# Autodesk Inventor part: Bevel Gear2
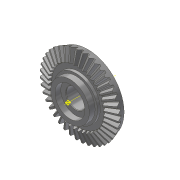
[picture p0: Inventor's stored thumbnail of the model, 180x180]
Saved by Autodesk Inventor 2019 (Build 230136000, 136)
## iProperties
Created: 2019-01
Part Number: Bevel Gear2
Material: Steel, Mild
Document SubType Name: Modeling
Designer: m.vorobev
Categories: <?xml version="1.0" encoding="UTF-16"?> <MemberInstance><Categories><FamilyTemplate><FamilyTemplateParameter ValueType="xs:double" Id="1" ObjectReferenceKey="da
Mass: 60.9118 g
Surface Area: 34.3074 cm^2
Volume: 7.7496 cm^3
Density: 7.86 g/cm^3
Appearance: Steel
CustomPartVersion: 1
Author: m.vorobev
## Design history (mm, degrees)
node "Top Point"
node "Mesh Plane2"
sketch "Teeth Body Sketch"
  geometry: L1 (0, 0)-(78.414, -32.531); L2 (78.414, -32.531)-(81.321, -24.225); L3 (81.321, -24.225)-(0, 0); L4 (80, -28)-(0, 0); L5 (55.286, -22.935)-(57.335, -17.079); L6 (78.414, -32.531)-(55.286, -22.935); L7 (81.321, -24.225)-(57.335, -17.079); L8 (0, -39.387)-(0, 6.564) reference; L9 (0, -28)-(81.321, -28)
  constraints: 16 end point, 4 point on line, 3 perpendicular, 2 collinear, 1 horizontal alignment, 1 vertical alignment
  dimensions: "d0" = 160 diameter of L4.start L8 (= da_de); "d1" = 156.82864 diameter of L1.end L8 (= da_dfe); "d2" = 162.6428 diameter of L2.end L8 (= da_dae); "d3" = 25 distance between parallel lines of L2 L5 (= da_b); "d4" = 24.22457 vertical distance of L2.end L1.start (= da_ve)
revolve "Teeth Body" sketch "Teeth Body Sketch" stored, may be unused: angle "d5" = 90 deg
node "Start Point"
node "Tooth Plane"
sketch "Start Sketch"
  geometry: L1 (0, -23.505)-(0, 10.645) reference; L2 (-1.283, -5.856)-(1.283, -5.856); A1 r 84.219 centre (-82.286, -28.909) between (-1.283, -5.856) and (-5.905, 6.57); A2 r 84.219 centre (82.286, -28.909) between (5.905, 6.57) and (1.283, -5.856); A3 r 248.807 centre (0, -242.167) between (5.905, 6.57) and (-5.905, 6.57); 1 further point
  constraints: 6 point on circle, 3 centre point, 3 symmetric about line, 2 end point, 1 coincident, 1 perpendicular, 1 other
  dimensions: "d7" = 84.21912 radius of A1 (= fd_rr); "d8" = 82.28596 horizontal distance of point (0, -242.167) A1.centre (= fd_x); "d9" = 213.25785 vertical distance of point (0, -242.167) A1.centre (= fd_y); "d57" = 248.80709 radius of A3 (= 0.5 x fd_dva + 0.3 x da_he); "d58" = 236.31109 distance from line of A3.centre L2 (= 0.5 x fd_dva - 1.12 x da_he)
node "End Point"
  node "End Plane"
sketch "3D Sketch Right"
  node "Helical Curve Right" dims "d65" = 388.94171 (computed from da_dm, da_delta, da_beta), "d66" = 31.5, "d67" = 160 (= da_de), "d68" = -12.34122 (= -da_delta), "d69" = 8.40411 (computed from fd_loft, da_delta)
node "End Plane Right"
sketch "End Sketch Right"
  geometry: L1 (0, -204.954)-(0, 39.264) reference; L2 (-0.899, -3.862)-(0.899, -3.862); A1 r 59.025 centre (-57.67, -20.019) between (-0.899, -3.862) and (-4.138, 4.847); A2 r 59.025 centre (57.67, -20.019) between (4.138, 4.847) and (0.899, -3.862); A3 r 174.377 centre (0, -169.481) between (4.138, 4.847) and (-4.138, 4.847); 1 further point
  constraints: 6 point on circle, 3 centre point, 3 symmetric about line, 2 end point, 1 coincident, 1 perpendicular, 1 other
  dimensions: "d70" = 57.67036 horizontal distance of A3.centre A1.centre (computed from fd_x, fd_ratio); "d71" = 149.46241 vertical distance of point (0, -169.481) A1.centre (computed from fd_y, fd_ratio); "d72" = 59.02523 radius of A1 (computed from fd_rr, fd_ratio); "d73" = 165.61934 distance from line of point (0, -169.481) L2 (computed from d58, fd_ratio); "d74" = 174.3772 radius of A3 (computed from d57, fd_ratio)
feature "Loft Right" sketch "End Sketch Right" dims "d75" = 0, "d77" = 0, "d79" = 0, "d80" = 90 deg, "d85" = 20, "d92" = 90 deg, "d93" = 90 deg, "da_teethtype" = 0 [user parameter]
sketch "3D Sketch Left"
  node "Helical Curve Left" dims "d26" = 388.94171 (computed from da_dm, da_delta, da_beta), "d27" = 8.40411 (computed from fd_loft, da_delta), "d28" = 160 (= da_de), "d29" = -12.34122 (= -da_delta)
node "End Plane Left"
sketch "End Sketch Left" dims "d56" = 19.01874 (derived)
  geometry: L1 (0, -205.693)-(0, 40.091) reference; L2 (-0.899, -3.776)-(0.899, -3.776); A1 r 59.025 centre (-57.67, -19.933) between (-0.899, -3.776) and (-4.138, 4.932); A2 r 59.025 centre (57.67, -19.933) between (4.138, 4.932) and (0.899, -3.776); A3 r 174.377 centre (0, -169.396) between (4.138, 4.932) and (-4.138, 4.932); 2 further points; 1 other entity
  constraints: 6 point on circle, 3 centre point, 3 symmetric about line, 2 end point, 1 coincident, 2 other
  dimensions: "d30" = 59.02523 radius of A1 (computed from fd_rr, fd_ratio); "d31" = 57.67036 horizontal distance of point (0, -169.396) A1.centre (computed from fd_x, fd_ratio); "d32" = 149.46241 vertical distance of A1.centre point (0, -169.396) (computed from fd_y, fd_ratio); "d61" = 174.3772 radius of A3 (computed from d57, fd_ratio); "d62" = 165.61934 distance from line of point (0, -169.396) L2 (computed from d58, fd_ratio)
feature "Loft Left" sketch "End Sketch Left" dims "d35" = 0, "d37" = 0, "d39" = 0, "d40" = 90 deg, "d84" = 10, "d90" = 90 deg, "d91" = 90 deg, "da_teethtype" = 0 [user parameter]
sketch "Body Sketch"
  geometry: L1 (0, -35.038)-(0, -19.531) reference; L2 (78.414, -32.531)-(55.286, -22.935) reference; L3 (55.286, -22.935)-(0, -22.935); L4 (78.414, -32.531)-(0, -32.531)
  constraints: 4 end point, 2 perpendicular, 2 point on line
revolve "Fix Body" sketch "Body Sketch" stored, may be unused: angle "d46" = 90 deg
sketch "Sketch6"
  geometry: L1 (80, -28)-(0, 0) reference; L2 (0, -37.8)-(0, 6.3) reference
feature "Pitch Diameter" sketch "Sketch6" dims angle "d47" = 90 deg
sketch "Sketch8"
  geometry: L1 (55.286, -22.935)-(57.335, -17.079) reference; L2 (81.321, -24.225)-(57.335, -17.079) reference; L3 (78.414, -32.531)-(81.321, -24.225) reference; L4 (78.414, -32.531)-(55.286, -22.935) reference; L5 (78.414, -32.531)-(75.072, -42.079); L6 (75.072, -42.079)-(55.286, -42.079); L7 (55.286, -42.079)-(55.286, -22.935); L8 (78.414, -32.531)-(55.286, -22.935); L9 (77.682, -32.531)-(78.398, -32.531) reference; L10 (78.398, -32.531)-(79.868, -32.531); L11 (79.868, -32.531)-(79.868, -37.903); L12 (79.868, -37.903)-(78.398, -37.903); L13 (78.398, -37.903)-(78.398, -32.531); L14 (55.286, -42.079)-(20, -42.079); L15 (20, -42.079)-(20, -22.935); L16 (20, -22.935)-(55.286, -22.935); L17 (55.286, -22.935)-(55.286, -42.079); L18 (20, -22.935)-(45, -22.935); L19 (45, -22.935)-(45, -17.079); L20 (45, -17.079)-(20, -17.079); L21 (20, -17.079)-(20, -22.935); L22 (31, -17.079)-(40, -17.079); L23 (40, -17.079)-(40, -5.079); L24 (40, -5.079)-(31, -5.079); L25 (31, -5.079)-(31, -17.079); L26 (0, -50.495)-(0, 8.416) reference; 2 further points
  constraints: 40 end point, 9 equal length, 5 horizontal, 4 perpendicular, 1 collinear, 1 point on line, 1 vertical
  dimensions: "d95" = 25 distance from line of L1.end L6; "d96" = 19.29 deg angle of L5 L13 (derived); "d97" = 40 diameter of L21 L26; "d98" = 62 diameter of L25 L26; "d99" = 12 distance of L24.end L22.start; "d100" = 25 distance between parallel lines of L14 L22; "d101" = 90 diameter of L19 L26; "d102" = 80 diameter of L23 L26; "d103" = 37 distance between parallel lines of L14 L24 (derived)
revolve "Revolution3" sketch "Sketch8" stored, may be unused: angle "d104" = 90 deg
delete_face "Delete Face1"
chamfer "Chamfer1" distance "d105" = 1; stored, may be unused: second distance "d106" = 2, angle "d107" = 45 deg
sketch "Sketch9"
  geometry: L1 (-22.3, 6)-(-7.299, 6); L2 (-7.299, 6)-(-7.299, -6); L3 (-7.299, -6)-(-22.3, -6); L4 (-22.3, -6)-(-22.3, 6); C1 r 21 at (0, 0) reference; 2 further points
  constraints: 8 end point, 2 parallel, 1 horizontal, 1 horizontal alignment, 1 midpoint, 1 perpendicular
  dimensions: "d108" = 12 distance of L3.end L1.start; "d109" = 43.3 dimension on C1 L4
extrude "Extrusion1" cut sketch "Sketch9" extent not by distance; stored distance "d110" = 0; taper "d111" = 0 deg
body "Solid1"
feature "Loft" dims "d17" = 0, "d18" = 90 deg, "d19" = 0, "d20" = 90 deg, "d89" = 0, "da_teethtype" = 0 [user parameter]
pattern_circular "Circular Pattern" dims angle "d22" = 360 deg, "d88" = 0, "da_teethtype" = 0 [user parameter]
pattern_circular "Circular Pattern Right" dims angle "d82" = 360 deg, "da_teethtype" = 0 [user parameter]
pattern_circular "Circular Pattern Left" dims angle "d42" = 360 deg, "da_teethtype" = 0 [user parameter]
sketch "End Sketch"
  geometry: L1 (0, -15.359)-(0, 6.983) reference; L2 (-0.899, -3.862)-(0.899, -3.862); A1 r 59.025 centre (-57.67, -20.019) between (-0.899, -3.862) and (-4.138, 4.847); A2 r 59.025 centre (57.67, -20.019) between (4.138, 4.847) and (0.899, -3.862); A3 r 174.377 centre (0, -169.481) between (4.138, 4.847) and (-4.138, 4.847); 1 further point
  constraints: 6 point on circle, 3 centre point, 3 symmetric about line, 2 end point, 1 coincident, 1 other
  dimensions: "d12" = 59.02523 radius of A1 (computed from fd_rr, fd_ratio); "d15" = 57.67036 horizontal distance of A1.centre point (0, -169.481) (computed from fd_x, fd_ratio); "d16" = 149.46241 vertical distance of A1.centre point (0, -169.481) (computed from fd_y, fd_ratio); "d59" = 174.3772 radius of A3 (computed from d57, fd_ratio); "d60" = 165.61934 distance from line of A3.centre L2 (computed from d58, fd_ratio)
body "Srf1"
other parameters: "da_b" = 25 [user parameter; used in 2 equation terms], "da_de" = 160 [user parameter; used in 4 equation terms], "da_dae" = 162.6428 [user parameter; used in 2 equation terms], "da_dfe" = 156.82864 [user parameter; used in 1 equation term], "da_le" = 84.75848 [user parameter; used in 1 equation term], "da_omega" = 90 deg [user parameter; used in 1 equation term], "da_beta" = 0 [user parameter; used in 2 equation terms], "da_delta" = 12.34122 [user parameter; used in 8 equation terms], "da_alpha" = 20 deg [user parameter; used in 2 equation terms], "da_he" = 8.8 [user parameter; used in 4 equation terms], "da_ve" = 24.22457 [user parameter; used in 1 equation term], "fd_dv" = 484.33417 (computed from da_de, da_delta) [user parameter; used in 1 equation term], "fd_dva" = 492.33417 (computed from da_dae, da_delta) [user parameter; used in 3 equation terms], "fd_dvb" = 455.12525 (computed from fd_dv, da_alpha) [user parameter; used in 2 equation terms], "da_zv" = 1210.83543 [user parameter; used in 1 equation term], "fd_loft" = 25.44 (= da_b + 0.05 x da_he) [user parameter; used in 4 equation terms], "fd_ratio" = 7.00853 (computed from da_le, fd_loft) [user parameter; used in 15 equation terms], "fd_rr" = 84.21912 (computed from fd_dd, fd_dvb) [user parameter; used in 6 equation terms], "fd_angle" = 0.13117 (computed from da_zv) [user parameter; used in 4 equation terms], "fd_x1" = 3.17641 (computed from da_dvw, fd_angle) [user parameter; used in 1 equation term], "fd_y1" = 242.14625 (computed from da_dvw, fd_angle) [user parameter; used in 1 equation term], "fd_x2" = 79.10955 (computed from fd_rr, fd_angle2, fd_angle) [user parameter; used in 1 equation term], "fd_y2" = 28.88841 (computed from fd_rr, fd_angle2, fd_angle) [user parameter; used in 1 equation term], "fd_x" = 82.28596 (= fd_x1 + fd_x2) [user parameter; used in 4 equation terms], "fd_y" = 213.25785 (= fd_y1 - fd_y2) [user parameter; used in 4 equation terms], "fd_angle2" = 3.37008 (computed from fd_dvb, fd_dd, da_alpha) [user parameter; used in 2 equation terms], "fd_dd" = 485.29417 (= fd_dva - 0.8 x da_he) [user parameter; used in 2 equation terms], "da_dvw" = 484.33417 [user parameter; used in 2 equation terms], "d11" = 25.44 (= fd_loft), "da_dm" = 136.40354 [user parameter; used in 2 equation terms], "da_x" = 0 [user parameter], "da_m" = 4 [user parameter], "d48" = 0, "d49" = 0, "d50" = 90 deg (= da_omega), "d51" = 4.5 deg (computed from da_z), "d52" = 0, "d53" = 0, "d54" = 0
